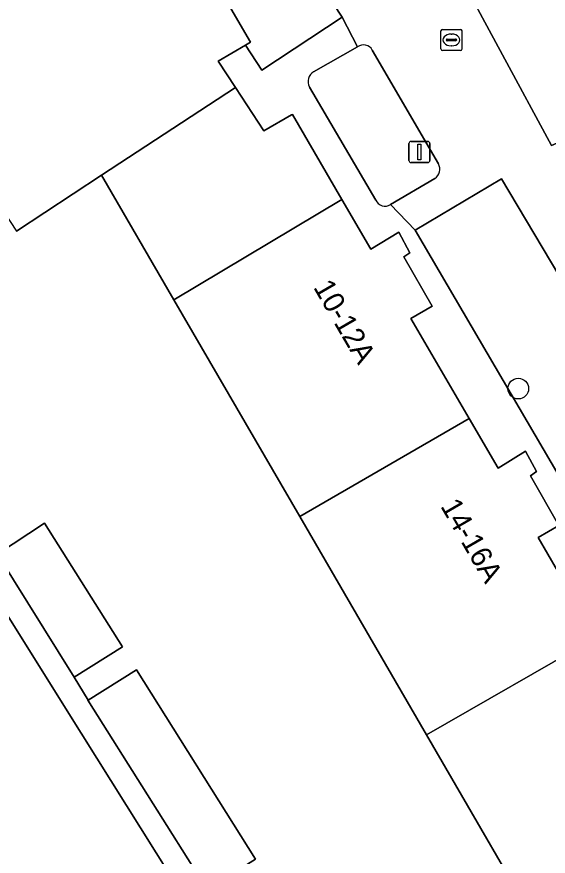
# Model space of a CAD drawing. Extents: x 161798 to 162385, y 382315 to 382833.
# Drawn here: x 162098.63 to 162123.82, y 382547.17 to 382586.96 of the extents above; entities that cross this region are included whole.
import ezdxf

# ---------------------------------------------------------------- set-up
doc = ezdxf.new("R2010")
doc.units = 0
for name, color, linetype in [('IMGEO_Boom', 7, 'Continuous'), ('IMGEO_Erf', 7, 'Continuous'), ('IMGEO_Groenvoorziening', 7, 'Continuous'), ('IMGEO_Kolk', 7, 'Continuous'), ('IMGEO_Lichtmast', 7, 'Continuous'), ('IMGEO_Pand', 7, 'Continuous'), ('IMGEO_Pand_nummerreeks', 7, 'Continuous'), ('IMGEO_Pand_overbouw', 7, 'Continuous'), ('IMGEO_Parkeervlak_open', 7, 'Continuous'), ('IMGEO_Voetpad_open', 7, 'Continuous'), ('IMGEO_Woonerf_open', 7, 'Continuous')]:
    doc.layers.add(name, color=color, linetype=linetype)

msp = doc.modelspace()

# ---------------------------------------------------------------- linework, layer by layer
at = {"layer": 'IMGEO_Boom'}
msp.add_circle((162122.401, 382569.337), 0.489, dxfattribs=at)
at = {"layer": 'IMGEO_Erf'}
for points in [[(162097.699, 382561.493), (162099.947, 382562.953), (162103.635, 382557.103), (162101.35, 382555.661), (162102.022, 382554.572), (162104.309, 382556.007), (162109.947, 382547.029), (162107.655, 382545.594), (162108.341, 382544.506), (162110.64, 382545.908), (162116.26, 382536.957), (162114.032, 382535.56), (162114.714, 382534.472), (162117.02, 382535.897), (162122.585, 382526.907), (162130.194, 382532.017), (162124.235, 382542.279), (162118.056, 382552.919), (162112.045, 382563.269), (162106.08, 382573.541), (162102.649, 382579.449), (162098.622, 382576.803)], [(162095.509, 382537.683), (162098.864, 382539.812), (162100.07, 382537.912), (162101.435, 382535.761), (162098.057, 382533.617), (162099.576, 382531.194), (162101.171, 382528.649), (162104.559, 382530.785), (162105.766, 382528.87), (162107.111, 382526.737), (162103.713, 382524.594), (162105.249, 382522.144), (162106.891, 382519.523), (162110.198, 382521.684), (162111.664, 382519.483), (162119.597, 382524.422), (162113.015, 382534.923), (162101.682, 382553.006), (162096.508, 382561.261)]]:
    msp.add_lwpolyline(points, dxfattribs=at)
at = {"layer": 'IMGEO_Groenvoorziening'}
for points in [[(162114.781, 382585.532), (162112.703, 382584.36)], [(162118.619, 382579.986), (162115.484, 382585.384)], [(162112.504, 382583.634), (162115.645, 382578.277)], [(162116.346, 382578.064), (162118.448, 382579.296)]]:
    msp.add_lwpolyline(points, dxfattribs=at)
for centre, radius, start, end in [((162115.069, 382585.158), 0.472, 28.6017, 127.621), ((162112.983, 382583.893), 0.545, 120.9788, 208.3641), ((162118.166, 382579.732), 0.519, 302.8969, 29.2652), ((162116.086, 382578.47), 0.482, 203.5887, 302.6084)]:
    msp.add_arc(centre, radius, start, end, dxfattribs=at)
at = {"layer": 'IMGEO_Kolk'}
for p, q in [((162118.733, 382585.44), (162118.733, 382586.292)), ((162118.808, 382586.366), (162119.66, 382586.366)), ((162119.221, 382586.146), (162119.246, 382586.146)), ((162119.734, 382586.292), (162119.734, 382585.44)), ((162118.992, 382585.86), (162118.992, 382585.872)), ((162119.43, 382585.823), (162119.032, 382585.823)), ((162119.035, 382585.909), (162119.433, 382585.909)), ((162119.476, 382585.872), (162119.476, 382585.86)), ((162119.66, 382585.366), (162118.808, 382585.366)), ((162119.244, 382585.586), (162119.219, 382585.586))]:
    msp.add_line(p, q, dxfattribs=at)
for points in [[(162118.733, 382585.44), (162118.733, 382586.292)], [(162118.808, 382586.366), (162119.66, 382586.366)], [(162119.734, 382586.292), (162119.734, 382585.44)], [(162119.66, 382585.366), (162118.808, 382585.366)]]:
    msp.add_lwpolyline(points, dxfattribs=at)
for centre, radius, start, end in [((162118.81, 382586.29), 0.0765, 91.552, 178.448), ((162118.81, 382586.29), 0.0765, 91.552, 178.448), ((162119.658, 382586.29), 0.0765, 1.552, 88.448), ((162119.658, 382586.29), 0.0765, 1.552, 88.448), ((162119.032, 382585.869), 0.0403, 85.8775, 175.7526), ((162119.029, 382585.859), 0.0366, 178.938, 274.7102), ((162119.433, 382585.866), 0.043, 264.8664, 352.4533), ((162119.437, 382585.871), 0.0386, 1.7309, 96.639), ((162118.81, 382585.442), 0.0765, 181.552, 268.448), ((162118.81, 382585.442), 0.0765, 181.552, 268.448), ((162119.658, 382585.442), 0.0765, 271.552, 358.448), ((162119.658, 382585.442), 0.0765, 271.552, 358.448)]:
    msp.add_arc(centre, radius, start, end, dxfattribs=at)
for centre, major_axis, ratio, start_param, end_param in [((162119.22, 382585.866), (-0.387, 0.002), 0.722429, 4.712389, 7.853982), ((162119.245, 382585.866), (-0.39, 0.002), 0.717154, 1.570796, 4.712389)]:
    msp.add_ellipse(centre, major_axis=major_axis, ratio=ratio, start_param=start_param, end_param=end_param, dxfattribs=at)
at = {"layer": 'IMGEO_Lichtmast'}
for p, q in [((162117.22, 382580.153), (162117.22, 382580.953)), ((162117.22, 382580.953), (162117.22, 382580.153)), ((162117.32, 382581.053), (162118.11, 382581.053)), ((162118.11, 382581.053), (162117.32, 382581.053)), ((162118.21, 382580.953), (162118.21, 382580.153)), ((162118.21, 382580.153), (162118.21, 382580.953)), ((162118.11, 382580.053), (162117.32, 382580.053)), ((162117.32, 382580.053), (162118.11, 382580.053))]:
    msp.add_line(p, q, dxfattribs=at)
msp.add_lwpolyline([(162117.64, 382580.928), (162117.79, 382580.928), (162117.79, 382580.178), (162117.64, 382580.178), (162117.64, 382580.928)], dxfattribs=at)
for centre, start, end in [((162117.32, 382580.953), 90, 180), ((162117.32, 382580.953), 90, 180), ((162118.11, 382580.953), 0, 90), ((162118.11, 382580.953), 360, 90), ((162117.32, 382580.153), 180, 270), ((162117.32, 382580.153), 180, 270), ((162118.11, 382580.153), 270, 0), ((162118.11, 382580.153), 270, 0)]:
    msp.add_arc(centre, 0.1, start, end, dxfattribs=at)
at = {"layer": 'IMGEO_Pand'}
for points in [[(162102.649, 382579.449), (162108.999, 382583.616), (162108.181, 382584.865), (162109.471, 382585.616), (162109.71, 382585.755), (162105.744, 382592.57), (162104.937, 382593.957), (162099.697, 382590.512), (162100.557, 382589.214), (162093.517, 382584.575), (162098.622, 382576.803)], [(162106.08, 382573.541), (162114.042, 382578.304), (162111.696, 382582.339), (162111.65, 382582.313), (162110.348, 382581.555), (162108.999, 382583.616), (162102.649, 382579.449)], [(162112.045, 382563.269), (162120.071, 382567.925), (162117.306, 382572.656), (162118.318, 382573.243), (162116.97, 382575.589), (162117.261, 382575.769), (162116.738, 382576.747), (162115.409, 382575.952), (162114.042, 382578.304), (162106.08, 382573.541)], [(162118.056, 382552.919), (162126.09, 382557.539), (162123.338, 382562.278), (162124.331, 382562.849), (162122.984, 382565.199), (162123.264, 382565.402), (162122.744, 382566.373), (162121.446, 382565.572), (162120.071, 382567.925), (162112.045, 382563.269)], [(162101.35, 382555.661), (162103.635, 382557.103), (162099.947, 382562.953), (162097.699, 382561.493)], [(162124.235, 382542.279), (162132.201, 382547.025), (162129.438, 382551.758), (162130.45, 382552.361), (162129.064, 382554.737), (162129.387, 382554.913), (162128.85, 382555.853), (162127.513, 382555.089), (162126.09, 382557.539), (162118.056, 382552.919)], [(162104.309, 382556.007), (162102.022, 382554.572), (162102.006, 382554.562), (162107.655, 382545.594), (162109.947, 382547.029)]]:
    msp.add_lwpolyline(points, close=True, dxfattribs=at)
at = {"layer": 'IMGEO_Pand_overbouw'}
msp.add_lwpolyline([(162109.471, 382585.616), (162110.249, 382584.437), (162114.048, 382586.943), (162108.961, 382594.691), (162105.744, 382592.57), (162109.71, 382585.755)], close=True, dxfattribs=at)
at = {"layer": 'IMGEO_Parkeervlak_open'}
for points in [[(162115.517, 382595.99), (162119.326, 382589.466), (162123.981, 382580.856), (162124.379, 382581.034), (162128.008, 382583.149), (162123.529, 382591.302)], [(162127.938, 382565.629), (162129.711, 382565.654), (162126.691, 382570.732), (162121.605, 382579.284), (162117.511, 382576.849), (162124.722, 382564.546), (162136.179, 382544.834), (162140.243, 382537.843), (162144.332, 382540.219), (162145.486, 382538.236), (162148.876, 382532.598), (162152.667, 382534.861), (162148.384, 382543.041), (162140.74, 382546.337), (162140.12, 382547.429), (162134.137, 382557.957), (162131.147, 382563.219)]]:
    msp.add_lwpolyline(points, dxfattribs=at)
at = {"layer": 'IMGEO_Voetpad_open'}
msp.add_lwpolyline([(162108.961, 382594.691), (162105.744, 382592.57), (162109.71, 382585.755), (162109.471, 382585.616), (162110.249, 382584.437), (162114.048, 382586.943)], close=True, dxfattribs=at)
for points in [[(162112.703, 382584.36), (162114.781, 382585.532), (162114.048, 382586.943), (162110.249, 382584.437), (162109.471, 382585.616), (162108.181, 382584.865), (162108.999, 382583.616), (162110.348, 382581.555), (162111.65, 382582.313), (162111.696, 382582.339), (162114.042, 382578.304), (162115.409, 382575.952), (162116.738, 382576.747), (162117.261, 382575.769), (162116.97, 382575.589), (162118.318, 382573.243), (162117.306, 382572.656), (162120.071, 382567.925), (162121.446, 382565.572), (162122.744, 382566.373), (162123.264, 382565.402), (162122.984, 382565.199), (162124.331, 382562.849), (162123.338, 382562.278), (162126.09, 382557.539)], [(162115.645, 382578.277), (162112.504, 382583.634)], [(162154.834, 382522.502), (162156.392, 382526.576), (162156.895, 382526.399), (162157.436, 382527.813), (162150.943, 382530.295), (162150.685, 382529.61), (162148.876, 382532.598), (162145.486, 382538.236), (162144.332, 382540.219), (162140.243, 382537.843), (162136.179, 382544.834), (162124.722, 382564.546), (162117.511, 382576.849), (162116.346, 382578.064)], [(162120.869, 382523.652), (162131.393, 382531.31), (162134.499, 382533.116), (162138.821, 382535.628), (162138.225, 382536.681), (162133.902, 382534.17), (162130.194, 382532.017), (162122.585, 382526.907), (162120.283, 382525.463), (162114.714, 382534.472), (162114.032, 382535.56), (162113.972, 382535.523), (162108.341, 382544.506), (162107.655, 382545.594), (162102.006, 382554.562), (162102.022, 382554.572), (162101.35, 382555.661), (162097.699, 382561.493)], [(162096.508, 382561.261), (162101.682, 382553.006), (162113.015, 382534.923), (162119.597, 382524.422)]]:
    msp.add_lwpolyline(points, dxfattribs=at)
for centre, radius, start, end in [((162112.983, 382583.893), 0.545, 120.9788, 208.3641), ((162116.086, 382578.47), 0.482, 203.5887, 302.6084)]:
    msp.add_arc(centre, radius, start, end, dxfattribs=at)
at = {"layer": 'IMGEO_Woonerf_open'}
for points in [[(162112.146, 382598.926), (162104.785, 382594.155), (162104.937, 382593.957), (162105.744, 382592.57), (162108.961, 382594.691), (162114.048, 382586.943), (162114.781, 382585.532)], [(162118.448, 382579.296), (162116.346, 382578.064), (162117.511, 382576.849), (162121.605, 382579.284), (162126.691, 382570.732), (162129.711, 382565.654), (162133.186, 382567.729), (162130.098, 382573.085), (162126.658, 382579.436), (162124.484, 382580.829), (162124.379, 382581.034), (162123.981, 382580.856), (162119.326, 382589.466)], [(162115.484, 382585.384), (162118.619, 382579.986)]]:
    msp.add_lwpolyline(points, dxfattribs=at)
for centre, radius, start, end in [((162115.069, 382585.158), 0.472, 28.6017, 127.621), ((162118.166, 382579.732), 0.519, 302.8969, 29.2652)]:
    msp.add_arc(centre, radius, start, end, dxfattribs=at)

# ---------------------------------------------------------------- texts
at = {"layer": 'IMGEO_Pand_nummerreeks'}
for s, rotation, p in [('10-12A', 300.1524, (162112.665, 382574.144)), ('14-16A', 300.0948, (162118.69, 382563.766))]:
    msp.add_text(s, height=1, rotation=rotation, dxfattribs=at).set_placement(p)

doc.saveas('drawing.dxf')
